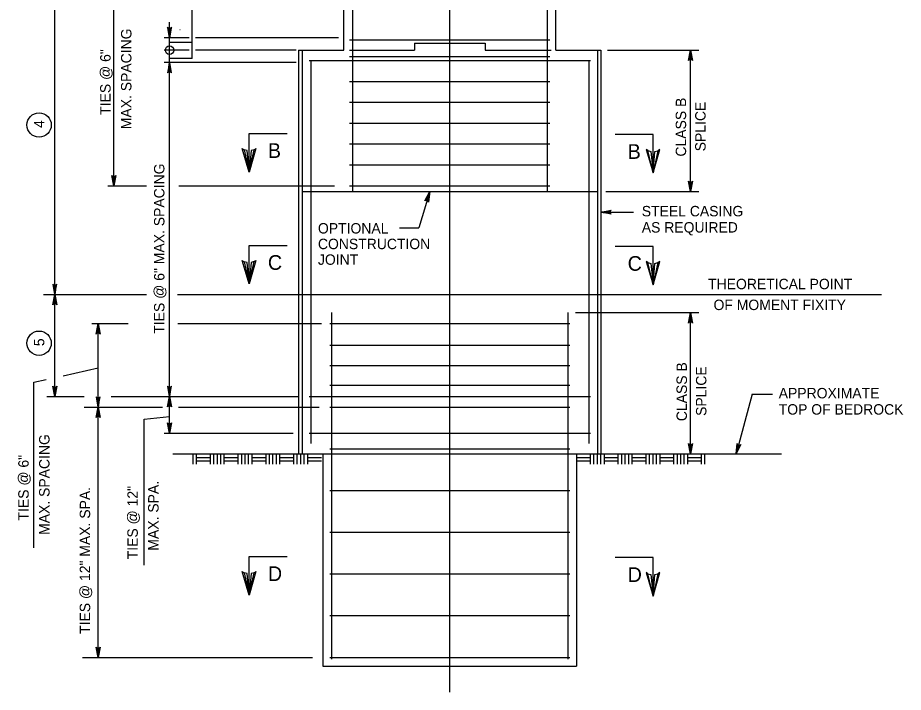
# Model space of a CAD drawing. Extents: x 646165 to 651486, y 296916 to 299292.
# Drawn here: x 650086.9 to 650341.8, y 297040.1 to 297234.1 of the extents above; entities that cross this region are included whole.
import ezdxf

# ---------------------------------------------------------------- set-up
doc = ezdxf.new("R2010")
doc.units = 0
for name, color, linetype in [('1', 7, 'Continuous'), ('50', 7, 'Continuous'), ('51', 7, 'Continuous'), ('52', 7, 'Continuous'), ('53', 7, 'Continuous'), ('54', 7, 'Continuous'), ('55', 7, 'Continuous'), ('56', 7, 'Continuous')]:
    doc.layers.add(name, color=color, linetype=linetype)

msp = doc.modelspace()

# ---------------------------------------------------------------- linework, layer by layer
at = {"layer": '1'}
for p, q in [((650153.51, 297200.8), (650164.44, 297200.8)), ((650153.51, 297189.73), (650153.51, 297200.8)), ((650269.75, 297200.53), (650258.82, 297200.53)), ((650269.75, 297189.46), (650269.75, 297200.53)), ((650153.51, 297168.6), (650164.44, 297168.6)), ((650153.51, 297157.53), (650153.51, 297168.6)), ((650269.75, 297168.34), (650258.82, 297168.34)), ((650269.75, 297157.27), (650269.75, 297168.34)), ((650153.51, 297079.09), (650164.44, 297079.09)), ((650153.51, 297068.03), (650153.51, 297079.09)), ((650269.75, 297078.83), (650258.82, 297078.83)), ((650269.75, 297067.76), (650269.75, 297078.83))]:
    msp.add_line(p, q, dxfattribs=at)
for points in [[(650154.99, 297196.15), (650154.14, 297195.91), (650153.51, 297189.73), (650154.99, 297196.15), (650155.5, 297196.48), (650153.51, 297189.73), (650152.96, 297195.9), (650152.12, 297196.13), (650153.51, 297189.73), (650151.56, 297196.48), (650152.12, 297196.13)], [(650268.28, 297195.88), (650269.12, 297195.64), (650269.75, 297189.46), (650268.28, 297195.88), (650267.76, 297196.21), (650269.75, 297189.46), (650270.31, 297195.64), (650271.14, 297195.86), (650269.75, 297189.46), (650271.7, 297196.21), (650271.14, 297195.86)], [(650154.99, 297163.95), (650154.14, 297163.72), (650153.51, 297157.53), (650154.99, 297163.95), (650155.5, 297164.28), (650153.51, 297157.53), (650152.96, 297163.71), (650152.12, 297163.94), (650153.51, 297157.53), (650151.56, 297164.28), (650152.12, 297163.94)], [(650268.28, 297163.69), (650269.12, 297163.45), (650269.75, 297157.27), (650268.28, 297163.69), (650267.76, 297164.02), (650269.75, 297157.27), (650270.31, 297163.44), (650271.14, 297163.67), (650269.75, 297157.27), (650271.7, 297164.02), (650271.14, 297163.67)], [(650154.99, 297074.45), (650154.14, 297074.21), (650153.51, 297068.03), (650154.99, 297074.45), (650155.5, 297074.78), (650153.51, 297068.03), (650152.96, 297074.2), (650152.12, 297074.43), (650153.51, 297068.03), (650151.56, 297074.78), (650152.12, 297074.43)], [(650268.28, 297074.18), (650269.12, 297073.94), (650269.75, 297067.76), (650268.28, 297074.18), (650267.76, 297074.51), (650269.75, 297067.76), (650270.31, 297073.94), (650271.14, 297074.16), (650269.75, 297067.76), (650271.7, 297074.51), (650271.14, 297074.16)]]:
    msp.add_lwpolyline(points, dxfattribs=at)
at = {"layer": '50'}
msp.add_line((650211.25, 297040.08), (650211.25, 297419.54), dxfattribs=at)
at = {"layer": '51'}
for p, q in [((650180.76, 297224.79), (650180.76, 297405.84)), ((650241.76, 297224.79), (650241.76, 297405.84)), ((650201.08, 297226.79), (650221.44, 297226.79)), ((650201.08, 297226.79), (650201.08, 297224.79)), ((650221.44, 297226.79), (650221.44, 297224.79)), ((650168.76, 297224.79), (650180.76, 297224.79)), ((650182.4, 297224.79), (650201.08, 297224.79)), ((650221.44, 297224.79), (650240.48, 297224.79)), ((650241.76, 297224.79), (650253.76, 297224.79)), ((650168.76, 297184.12), (650253.76, 297184.12)), ((650168.76, 297108.62), (650174.76, 297108.62)), ((650174.76, 297108.62), (650174.76, 297047.62)), ((650247.76, 297108.62), (650247.76, 297047.62)), ((650247.76, 297108.62), (650253.76, 297108.62)), ((650174.76, 297047.62), (650247.76, 297047.62)), ((650180.76, 297047.62), (650241.76, 297047.62))]:
    msp.add_line(p, q, dxfattribs=at)
at = {"layer": '52'}
for p, q in [((650114.63, 297185.79), (650114.63, 297399.84)), ((650137.1, 297222.41), (650137.1, 297275.01)), ((650097.63, 297125.12), (650097.63, 297253.95)), ((650130.63, 297114.62), (650130.63, 297232.85)), ((650136.32, 297228.37), (650129.06, 297228.37)), ((650137.1, 297227), (650130.63, 297227)), ((650179.28, 297228.37), (650138.1, 297228.37)), ((650136.32, 297224.79), (650129.06, 297224.79)), ((650167.06, 297224.79), (650138.1, 297224.79)), ((650256.68, 297224.79), (650282.93, 297224.79)), ((650280.53, 297184.12), (650280.53, 297224.79)), ((650167.06, 297221.21), (650129.06, 297221.21)), ((650137.1, 297222.41), (650130.63, 297222.41)), ((650112.83, 297185.79), (650124.04, 297185.79)), ((650133.34, 297185.79), (650178.13, 297185.79)), ((650205.5, 297184.12), (650202.33, 297173.67)), ((650256.2, 297184.12), (650282.93, 297184.12)), ((650254.76, 297178.16), (650264.1, 297178.16)), ((650196.8, 297173.67), (650202.33, 297173.67)), ((650094.36, 297154.51), (650124.04, 297154.51)), ((650132.93, 297154.51), (650335.45, 297154.51)), ((650247.47, 297149.28), (650282.93, 297149.28)), ((650280.53, 297108.62), (650280.53, 297149.28)), ((650108.29, 297146.12), (650118.7, 297146.12)), ((650110.1, 297050.12), (650110.1, 297146.12)), ((650132.98, 297146.12), (650174.34, 297146.12)), ((650100.03, 297131.14), (650110.1, 297133.38)), ((650091.61, 297129.27), (650095.09, 297130.04)), ((650091.61, 297081.64), (650091.61, 297129.27)), ((650095.31, 297125.12), (650106.03, 297125.12)), ((650113.86, 297125.12), (650167.66, 297125.12)), ((650298.24, 297125.8), (650293.69, 297108.62)), ((650298.24, 297125.8), (650304.12, 297125.8)), ((650106.03, 297122.12), (650128.59, 297122.12)), ((650133.17, 297122.12), (650173.71, 297122.12)), ((650123.33, 297118.66), (650130.63, 297119.42)), ((650123.33, 297076.69), (650123.33, 297118.66)), ((650129.06, 297114.62), (650166.16, 297114.62)), ((650105.61, 297050.12), (650171.79, 297050.12))]:
    msp.add_line(p, q, dxfattribs=at)
for points in [[(650130.65, 297228.37), (650131.21, 297231.35), (650131.13, 297231.24), (650131.05, 297231.12), (650130.95, 297231.07), (650130.85, 297231.01), (650130.75, 297230.99), (650130.65, 297230.97), (650130.55, 297230.99), (650130.45, 297231.01), (650130.35, 297231.07), (650130.25, 297231.12), (650130.17, 297231.24), (650130.09, 297231.35), (650130.65, 297228.37), (650130.17, 297231.24), (650130.25, 297231.12), (650130.65, 297228.37), (650130.35, 297231.07), (650130.45, 297231.01), (650130.65, 297228.37), (650130.55, 297230.99), (650130.65, 297230.97), (650130.65, 297228.37), (650130.75, 297230.99), (650130.85, 297231.01), (650130.65, 297228.37), (650130.95, 297231.07), (650131.05, 297231.12), (650130.65, 297228.37), (650131.13, 297231.24)], [(650280.53, 297224.79), (650281.09, 297221.81), (650281.01, 297221.92), (650280.93, 297222.04), (650280.83, 297222.1), (650280.73, 297222.15), (650280.63, 297222.17), (650280.53, 297222.19), (650280.43, 297222.17), (650280.33, 297222.15), (650280.23, 297222.1), (650280.13, 297222.04), (650280.05, 297221.92), (650279.97, 297221.81), (650280.53, 297224.79), (650280.05, 297221.92), (650280.13, 297222.04), (650280.53, 297224.79), (650280.23, 297222.1), (650280.33, 297222.15), (650280.53, 297224.79), (650280.43, 297222.17), (650280.53, 297222.19), (650280.53, 297224.79), (650280.63, 297222.17), (650280.73, 297222.15), (650280.53, 297224.79), (650280.83, 297222.1), (650280.93, 297222.04), (650280.53, 297224.79), (650281.01, 297221.92)], [(650130.63, 297221.22), (650130.07, 297218.23), (650130.15, 297218.35), (650130.23, 297218.46), (650130.33, 297218.52), (650130.43, 297218.58), (650130.53, 297218.6), (650130.63, 297218.62), (650130.73, 297218.6), (650130.83, 297218.58), (650130.93, 297218.52), (650131.03, 297218.46), (650131.11, 297218.35), (650131.19, 297218.23), (650130.63, 297221.22), (650131.11, 297218.35), (650131.03, 297218.46), (650130.63, 297221.22), (650130.93, 297218.52), (650130.83, 297218.58), (650130.63, 297221.22), (650130.73, 297218.6), (650130.63, 297218.62), (650130.63, 297221.22), (650130.53, 297218.6), (650130.43, 297218.58), (650130.63, 297221.22), (650130.33, 297218.52), (650130.23, 297218.46), (650130.63, 297221.22), (650130.15, 297218.35)], [(650114.63, 297185.79), (650114.07, 297188.77), (650114.15, 297188.66), (650114.23, 297188.54), (650114.33, 297188.48), (650114.43, 297188.42), (650114.53, 297188.41), (650114.63, 297188.39), (650114.73, 297188.41), (650114.83, 297188.42), (650114.93, 297188.48), (650115.03, 297188.54), (650115.11, 297188.66), (650115.19, 297188.77), (650114.63, 297185.79), (650115.11, 297188.66), (650115.03, 297188.54), (650114.63, 297185.79), (650114.93, 297188.48), (650114.83, 297188.42), (650114.63, 297185.79), (650114.73, 297188.41), (650114.63, 297188.39), (650114.63, 297185.79), (650114.53, 297188.41), (650114.43, 297188.42), (650114.63, 297185.79), (650114.33, 297188.48), (650114.23, 297188.54), (650114.63, 297185.79), (650114.15, 297188.66)], [(650280.53, 297184.12), (650279.97, 297187.1), (650280.05, 297186.99), (650280.13, 297186.87), (650280.23, 297186.81), (650280.33, 297186.76), (650280.43, 297186.74), (650280.53, 297186.72), (650280.63, 297186.74), (650280.73, 297186.76), (650280.83, 297186.81), (650280.93, 297186.87), (650281.01, 297186.99), (650281.09, 297187.1), (650280.53, 297184.12), (650281.01, 297186.99), (650280.93, 297186.87), (650280.53, 297184.12), (650280.83, 297186.81), (650280.73, 297186.76), (650280.53, 297184.12), (650280.63, 297186.74), (650280.53, 297186.72), (650280.53, 297184.12), (650280.43, 297186.74), (650280.33, 297186.76), (650280.53, 297184.12), (650280.23, 297186.81), (650280.13, 297186.87), (650280.53, 297184.12), (650280.05, 297186.99)], [(650205.5, 297184.12), (650205.17, 297181.1), (650205.08, 297181.37), (650204.93, 297181.54), (650204.75, 297181.63), (650204.54, 297181.66), (650204.32, 297181.6), (650204.1, 297181.43), (650205.5, 297184.12), (650204.32, 297181.6), (650204.54, 297181.66), (650205.5, 297184.12), (650204.75, 297181.63), (650204.93, 297181.54), (650205.5, 297184.12), (650205.08, 297181.37)], [(650254.76, 297178.16), (650257.74, 297178.72), (650257.51, 297178.56), (650257.39, 297178.36), (650257.36, 297178.16), (650257.39, 297177.96), (650257.51, 297177.76), (650257.74, 297177.6), (650254.76, 297178.16), (650257.51, 297177.76), (650257.39, 297177.96), (650254.76, 297178.16), (650257.36, 297178.16), (650257.39, 297178.36), (650254.76, 297178.16), (650257.51, 297178.56)], [(650097.63, 297154.51), (650098.19, 297157.5), (650098.11, 297157.38), (650098.03, 297157.27), (650097.93, 297157.21), (650097.83, 297157.15), (650097.73, 297157.13), (650097.63, 297157.11), (650097.53, 297157.13), (650097.43, 297157.15), (650097.33, 297157.21), (650097.23, 297157.27), (650097.15, 297157.38), (650097.07, 297157.5), (650097.63, 297154.51), (650097.15, 297157.38), (650097.23, 297157.27), (650097.63, 297154.51), (650097.33, 297157.21), (650097.43, 297157.15), (650097.63, 297154.51), (650097.53, 297157.13), (650097.63, 297157.11), (650097.63, 297154.51), (650097.73, 297157.13), (650097.83, 297157.15), (650097.63, 297154.51), (650097.93, 297157.21), (650098.03, 297157.27), (650097.63, 297154.51), (650098.11, 297157.38)], [(650097.63, 297154.51), (650098.19, 297151.53), (650098.11, 297151.65), (650098.03, 297151.76), (650097.93, 297151.82), (650097.83, 297151.88), (650097.73, 297151.9), (650097.63, 297151.91), (650097.53, 297151.9), (650097.43, 297151.88), (650097.33, 297151.82), (650097.23, 297151.76), (650097.15, 297151.65), (650097.07, 297151.53), (650097.63, 297154.51), (650097.15, 297151.65), (650097.23, 297151.76), (650097.63, 297154.51), (650097.33, 297151.82), (650097.43, 297151.88), (650097.63, 297154.51), (650097.53, 297151.9), (650097.63, 297151.91), (650097.63, 297154.51), (650097.73, 297151.9), (650097.83, 297151.88), (650097.63, 297154.51), (650097.93, 297151.82), (650098.03, 297151.76), (650097.63, 297154.51), (650098.11, 297151.65)], [(650280.53, 297149.28), (650281.09, 297146.3), (650281.01, 297146.42), (650280.93, 297146.53), (650280.83, 297146.59), (650280.73, 297146.65), (650280.63, 297146.67), (650280.53, 297146.68), (650280.43, 297146.67), (650280.33, 297146.65), (650280.23, 297146.59), (650280.13, 297146.53), (650280.05, 297146.42), (650279.97, 297146.3), (650280.53, 297149.28), (650280.05, 297146.42), (650280.13, 297146.53), (650280.53, 297149.28), (650280.23, 297146.59), (650280.33, 297146.65), (650280.53, 297149.28), (650280.43, 297146.67), (650280.53, 297146.68), (650280.53, 297149.28), (650280.63, 297146.67), (650280.73, 297146.65), (650280.53, 297149.28), (650280.83, 297146.59), (650280.93, 297146.53), (650280.53, 297149.28), (650281.01, 297146.42)], [(650110.1, 297146.12), (650110.66, 297143.13), (650110.58, 297143.25), (650110.5, 297143.36), (650110.4, 297143.42), (650110.3, 297143.48), (650110.2, 297143.5), (650110.1, 297143.52), (650110, 297143.5), (650109.9, 297143.48), (650109.8, 297143.42), (650109.7, 297143.36), (650109.62, 297143.25), (650109.54, 297143.13), (650110.1, 297146.12), (650109.62, 297143.25), (650109.7, 297143.36), (650110.1, 297146.12), (650109.8, 297143.42), (650109.9, 297143.48), (650110.1, 297146.12), (650110, 297143.5), (650110.1, 297143.52), (650110.1, 297146.12), (650110.2, 297143.5), (650110.3, 297143.48), (650110.1, 297146.12), (650110.4, 297143.42), (650110.5, 297143.36), (650110.1, 297146.12), (650110.58, 297143.25)], [(650097.63, 297125.12), (650097.07, 297128.1), (650097.15, 297127.99), (650097.23, 297127.87), (650097.33, 297127.82), (650097.43, 297127.76), (650097.53, 297127.74), (650097.63, 297127.72), (650097.73, 297127.74), (650097.83, 297127.76), (650097.93, 297127.82), (650098.03, 297127.87), (650098.11, 297127.99), (650098.19, 297128.1), (650097.63, 297125.12), (650098.11, 297127.99), (650098.03, 297127.87), (650097.63, 297125.12), (650097.93, 297127.82), (650097.83, 297127.76), (650097.63, 297125.12), (650097.73, 297127.74), (650097.63, 297127.72), (650097.63, 297125.12), (650097.53, 297127.74), (650097.43, 297127.76), (650097.63, 297125.12), (650097.33, 297127.82), (650097.23, 297127.87), (650097.63, 297125.12), (650097.15, 297127.99)], [(650130.63, 297125.12), (650131.19, 297128.1), (650131.11, 297127.99), (650131.03, 297127.87), (650130.93, 297127.82), (650130.83, 297127.76), (650130.73, 297127.74), (650130.63, 297127.72), (650130.53, 297127.74), (650130.43, 297127.76), (650130.33, 297127.82), (650130.23, 297127.87), (650130.15, 297127.99), (650130.07, 297128.1), (650130.63, 297125.12), (650130.15, 297127.99), (650130.23, 297127.87), (650130.63, 297125.12), (650130.33, 297127.82), (650130.43, 297127.76), (650130.63, 297125.12), (650130.53, 297127.74), (650130.63, 297127.72), (650130.63, 297125.12), (650130.73, 297127.74), (650130.83, 297127.76), (650130.63, 297125.12), (650130.93, 297127.82), (650131.03, 297127.87), (650130.63, 297125.12), (650131.11, 297127.99)], [(650110.1, 297122.12), (650110.66, 297125.1), (650110.58, 297124.98), (650110.5, 297124.87), (650110.4, 297124.81), (650110.3, 297124.75), (650110.2, 297124.73), (650110.1, 297124.72), (650110, 297124.73), (650109.9, 297124.75), (650109.8, 297124.81), (650109.7, 297124.87), (650109.62, 297124.98), (650109.54, 297125.1), (650110.1, 297122.12), (650109.62, 297124.98), (650109.7, 297124.87), (650110.1, 297122.12), (650109.8, 297124.81), (650109.9, 297124.75), (650110.1, 297122.12), (650110, 297124.73), (650110.1, 297124.72), (650110.1, 297122.12), (650110.2, 297124.73), (650110.3, 297124.75), (650110.1, 297122.12), (650110.4, 297124.81), (650110.5, 297124.87), (650110.1, 297122.12), (650110.58, 297124.98)], [(650130.63, 297125.12), (650131.19, 297122.14), (650131.11, 297122.25), (650131.03, 297122.37), (650130.93, 297122.43), (650130.83, 297122.49), (650130.73, 297122.5), (650130.63, 297122.52), (650130.53, 297122.5), (650130.43, 297122.49), (650130.33, 297122.43), (650130.23, 297122.37), (650130.15, 297122.25), (650130.07, 297122.14), (650130.63, 297125.12), (650130.15, 297122.25), (650130.23, 297122.37), (650130.63, 297125.12), (650130.33, 297122.43), (650130.43, 297122.49), (650130.63, 297125.12), (650130.53, 297122.5), (650130.63, 297122.52), (650130.63, 297125.12), (650130.73, 297122.5), (650130.83, 297122.49), (650130.63, 297125.12), (650130.93, 297122.43), (650131.03, 297122.37), (650130.63, 297125.12), (650131.11, 297122.25)], [(650110.1, 297122.12), (650110.66, 297119.13), (650110.58, 297119.25), (650110.5, 297119.36), (650110.4, 297119.42), (650110.3, 297119.48), (650110.2, 297119.5), (650110.1, 297119.52), (650110, 297119.5), (650109.9, 297119.48), (650109.8, 297119.42), (650109.7, 297119.36), (650109.62, 297119.25), (650109.54, 297119.13), (650110.1, 297122.12), (650109.62, 297119.25), (650109.7, 297119.36), (650110.1, 297122.12), (650109.8, 297119.42), (650109.9, 297119.48), (650110.1, 297122.12), (650110, 297119.5), (650110.1, 297119.52), (650110.1, 297122.12), (650110.2, 297119.5), (650110.3, 297119.48), (650110.1, 297122.12), (650110.4, 297119.42), (650110.5, 297119.36), (650110.1, 297122.12), (650110.58, 297119.25)], [(650130.63, 297114.62), (650130.07, 297117.6), (650130.15, 297117.48), (650130.23, 297117.37), (650130.33, 297117.31), (650130.43, 297117.25), (650130.53, 297117.23), (650130.63, 297117.22), (650130.73, 297117.23), (650130.83, 297117.25), (650130.93, 297117.31), (650131.03, 297117.37), (650131.11, 297117.48), (650131.19, 297117.6), (650130.63, 297114.62), (650131.11, 297117.48), (650131.03, 297117.37), (650130.63, 297114.62), (650130.93, 297117.31), (650130.83, 297117.25), (650130.63, 297114.62), (650130.73, 297117.23), (650130.63, 297117.22), (650130.63, 297114.62), (650130.53, 297117.23), (650130.43, 297117.25), (650130.63, 297114.62), (650130.33, 297117.31), (650130.23, 297117.37), (650130.63, 297114.62), (650130.15, 297117.48)], [(650280.53, 297108.62), (650279.97, 297111.6), (650280.05, 297111.48), (650280.13, 297111.37), (650280.23, 297111.31), (650280.33, 297111.25), (650280.43, 297111.23), (650280.53, 297111.22), (650280.63, 297111.23), (650280.73, 297111.25), (650280.83, 297111.31), (650280.93, 297111.37), (650281.01, 297111.48), (650281.09, 297111.6), (650280.53, 297108.62), (650281.01, 297111.48), (650280.93, 297111.37), (650280.53, 297108.62), (650280.83, 297111.31), (650280.73, 297111.25), (650280.53, 297108.62), (650280.63, 297111.23), (650280.53, 297111.22), (650280.53, 297108.62), (650280.43, 297111.23), (650280.33, 297111.25), (650280.53, 297108.62), (650280.23, 297111.31), (650280.13, 297111.37), (650280.53, 297108.62), (650280.05, 297111.48)], [(650293.69, 297108.62), (650293.91, 297111.64), (650293.96, 297111.51), (650294.01, 297111.38), (650294.09, 297111.3), (650294.17, 297111.21), (650294.26, 297111.17), (650294.36, 297111.13), (650294.46, 297111.12), (650294.56, 297111.11), (650294.67, 297111.14), (650294.78, 297111.18), (650294.89, 297111.27), (650294.99, 297111.36), (650293.69, 297108.62), (650294.89, 297111.27), (650294.78, 297111.18), (650293.69, 297108.62), (650294.67, 297111.14), (650294.56, 297111.11), (650293.69, 297108.62), (650294.46, 297111.12), (650294.36, 297111.13), (650293.69, 297108.62), (650294.26, 297111.17), (650294.17, 297111.21), (650293.69, 297108.62), (650294.09, 297111.3), (650294.01, 297111.38), (650293.69, 297108.62), (650293.96, 297111.51)], [(650110.1, 297050.12), (650109.54, 297053.1), (650109.62, 297052.98), (650109.7, 297052.87), (650109.8, 297052.81), (650109.9, 297052.75), (650110, 297052.73), (650110.1, 297052.72), (650110.2, 297052.73), (650110.3, 297052.75), (650110.4, 297052.81), (650110.5, 297052.87), (650110.58, 297052.98), (650110.66, 297053.1), (650110.1, 297050.12), (650110.58, 297052.98), (650110.5, 297052.87), (650110.1, 297050.12), (650110.4, 297052.81), (650110.3, 297052.75), (650110.1, 297050.12), (650110.2, 297052.73), (650110.1, 297052.72), (650110.1, 297050.12), (650110, 297052.73), (650109.9, 297052.75), (650110.1, 297050.12), (650109.8, 297052.81), (650109.7, 297052.87), (650110.1, 297050.12), (650109.62, 297052.98)]]:
    msp.add_lwpolyline(points, dxfattribs=at)
for centre in [(650093.1, 297203.27), (650093.1, 297140.49)]:
    msp.add_circle(centre, 3.5, dxfattribs=at)
at = {"layer": '54'}
for p, q in [((650183.26, 297325.94), (650183.26, 297184.12)), ((650239.26, 297292.61), (650239.26, 297184.12)), ((650182.42, 297227.79), (650240.09, 297227.79)), ((650170.76, 297221.79), (650251.76, 297221.79)), ((650171.26, 297221.79), (650171.26, 297111.62)), ((650182.42, 297222.91), (650240.09, 297222.91)), ((650251.26, 297221.79), (650251.26, 297111.62)), ((650182.42, 297215.79), (650240.09, 297215.79)), ((650182.42, 297209.79), (650240.09, 297209.79)), ((650182.42, 297203.79), (650240.09, 297203.79)), ((650182.42, 297197.79), (650240.09, 297197.79)), ((650182.42, 297191.79), (650240.09, 297191.79)), ((650182.42, 297185.79), (650240.09, 297185.79)), ((650177.26, 297149.28), (650177.26, 297049.62)), ((650245.26, 297149.28), (650245.26, 297049.62)), ((650176.76, 297146.12), (650245.76, 297146.12)), ((650176.76, 297139.92), (650245.76, 297139.92)), ((650176.76, 297134.12), (650245.76, 297134.12)), ((650176.76, 297128.42), (650245.76, 297128.42)), ((650170.76, 297125.12), (650251.76, 297125.12)), ((650176.76, 297122.12), (650245.76, 297122.12)), ((650170.76, 297114.62), (650251.76, 297114.62)), ((650176.76, 297110.12), (650245.76, 297110.12)), ((650176.76, 297098.12), (650245.76, 297098.12)), ((650176.76, 297086.12), (650245.76, 297086.12)), ((650176.76, 297074.12), (650245.76, 297074.12)), ((650176.76, 297062.12), (650245.76, 297062.12)), ((650176.76, 297050.12), (650245.76, 297050.12))]:
    msp.add_line(p, q, dxfattribs=at)
msp.add_circle((650130.64, 297224.76), 1.22, dxfattribs=at)
at = {"layer": '55'}
for p, q in [((650167.76, 297224.79), (650167.76, 297108.62)), ((650167.76, 297224.79), (650168.76, 297224.79)), ((650168.76, 297224.79), (650168.76, 297108.62)), ((650253.76, 297224.79), (650253.76, 297108.62)), ((650253.76, 297224.79), (650254.76, 297224.79)), ((650254.76, 297224.79), (650254.76, 297108.62)), ((650167.76, 297108.62), (650168.76, 297108.62)), ((650253.76, 297108.62), (650254.76, 297108.62))]:
    msp.add_line(p, q, dxfattribs=at)
at = {"layer": '56'}
for p, q in [((650133.67, 297230.63), (650133.63, 297230.67)), ((650131.59, 297108.62), (650306.74, 297108.62)), ((650137.39, 297105.65), (650137.39, 297108.62)), ((650138.39, 297105.65), (650138.39, 297108.62)), ((650138.39, 297107.62), (650142.39, 297107.62)), ((650138.39, 297106.62), (650142.39, 297106.62)), ((650142.39, 297105.65), (650142.39, 297108.62)), ((650143.39, 297105.65), (650143.39, 297108.62)), ((650144.39, 297105.65), (650144.39, 297108.62)), ((650145.39, 297105.65), (650145.39, 297108.62)), ((650146.39, 297105.65), (650146.39, 297108.62)), ((650146.39, 297107.62), (650150.39, 297107.62)), ((650146.39, 297106.62), (650150.39, 297106.62)), ((650150.39, 297105.65), (650150.39, 297108.62)), ((650151.39, 297105.65), (650151.39, 297108.62)), ((650152.39, 297105.65), (650152.39, 297108.62)), ((650153.39, 297105.65), (650153.39, 297108.62)), ((650154.39, 297105.65), (650154.39, 297108.62)), ((650154.39, 297107.62), (650158.39, 297107.62)), ((650154.39, 297106.62), (650158.39, 297106.62)), ((650158.39, 297105.65), (650158.39, 297108.62)), ((650159.39, 297105.65), (650159.39, 297108.62)), ((650160.39, 297105.65), (650160.39, 297108.62)), ((650161.39, 297105.65), (650161.39, 297108.62)), ((650162.39, 297105.65), (650162.39, 297108.62)), ((650162.39, 297107.62), (650166.39, 297107.62)), ((650162.39, 297106.62), (650166.39, 297106.62)), ((650166.39, 297105.65), (650166.39, 297108.62)), ((650167.39, 297105.65), (650167.39, 297108.62)), ((650168.39, 297105.65), (650168.39, 297108.62)), ((650169.39, 297105.65), (650169.39, 297108.62)), ((650170.39, 297105.65), (650170.39, 297108.62)), ((650170.39, 297107.62), (650174.39, 297107.62)), ((650170.39, 297106.62), (650174.39, 297106.62)), ((650247.75, 297107.62), (650251.75, 297107.62)), ((650247.75, 297106.62), (650251.75, 297106.62)), ((650251.75, 297105.65), (650251.75, 297108.62)), ((650252.75, 297105.65), (650252.75, 297108.62)), ((650253.75, 297105.65), (650253.75, 297108.62)), ((650254.75, 297105.65), (650254.75, 297108.62)), ((650255.75, 297105.65), (650255.75, 297108.62)), ((650255.75, 297107.62), (650259.75, 297107.62)), ((650255.75, 297106.62), (650259.75, 297106.62)), ((650259.75, 297105.65), (650259.75, 297108.62)), ((650260.75, 297105.65), (650260.75, 297108.62)), ((650261.75, 297105.65), (650261.75, 297108.62)), ((650262.75, 297105.65), (650262.75, 297108.62)), ((650263.75, 297105.65), (650263.75, 297108.62)), ((650263.75, 297107.62), (650267.75, 297107.62)), ((650263.75, 297106.62), (650267.75, 297106.62)), ((650267.75, 297105.65), (650267.75, 297108.62)), ((650268.75, 297105.65), (650268.75, 297108.62)), ((650269.75, 297105.65), (650269.75, 297108.62)), ((650270.75, 297105.65), (650270.75, 297108.62)), ((650271.75, 297105.65), (650271.75, 297108.62)), ((650271.75, 297107.62), (650275.75, 297107.62)), ((650271.75, 297106.62), (650275.75, 297106.62)), ((650275.75, 297105.65), (650275.75, 297108.62)), ((650276.75, 297105.65), (650276.75, 297108.62)), ((650277.75, 297105.65), (650277.75, 297108.62)), ((650278.75, 297105.65), (650278.75, 297108.62)), ((650279.75, 297105.65), (650279.75, 297108.62)), ((650279.75, 297107.62), (650283.75, 297107.62)), ((650279.75, 297106.62), (650283.69, 297106.62)), ((650283.69, 297105.65), (650283.69, 297108.62)), ((650284.69, 297105.65), (650284.69, 297108.62))]:
    msp.add_line(p, q, dxfattribs=at)

# ---------------------------------------------------------------- texts
at = {"layer": '1'}
for s, p in [('B', (650158.93, 297193.78)), ('B', (650262.45, 297193.51)), ('C', (650158.93, 297161.59)), ('C', (650262.45, 297161.32)), ('D', (650158.93, 297072.08)), ('D', (650262.45, 297071.81))]:
    msp.add_text(s, height=4.23, dxfattribs=at).set_placement(p)
at = {"layer": '53'}
for s, p in [('MAX. SPACING', (650119.67, 297202.04)), ('TIES @ 6"', (650113.67, 297206.18)), ('CLASS B', (650279.27, 297194.17)), ('SPLICE', (650284.87, 297195.69)), ('4', (650094.6, 297202.42)), ('TIES @ 6" MAX. SPACING', (650129.16, 297143.22)), ('5', (650094.6, 297139.64)), ('CLASS B', (650279.5, 297118.06)), ('SPLICE', (650285.1, 297119.57)), ('MAX. SPACING', (650096.1, 297085.35)), ('TIES @ 6"', (650090.1, 297089.49)), ('TIES @ 12" MAX. SPA.', (650107.79, 297056.87)), ('TIES @ 12"', (650121.5, 297078.33)), ('MAX. SPA.', (650127.47, 297080.82))]:
    msp.add_text(s, height=3, rotation=90, dxfattribs=at).set_placement(p)
for s, p in [('STEEL CASING', (650266.51, 297176.98)), ('OPTIONAL', (650173.33, 297172.04)), ('AS REQUIRED', (650266.51, 297172.32)), ('CONSTRUCTION', (650173.33, 297167.54)), ('JOINT', (650173.33, 297163.04)), ('THEORETICAL POINT', (650285.6, 297156.02)), ('OF MOMENT FIXITY', (650287.15, 297150.02)), ('APPROXIMATE ', (650305.91, 297124.62)), ('TOP OF BEDROCK', (650305.91, 297119.95))]:
    msp.add_text(s, height=3, dxfattribs=at).set_placement(p)

doc.saveas('drawing.dxf')
